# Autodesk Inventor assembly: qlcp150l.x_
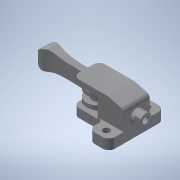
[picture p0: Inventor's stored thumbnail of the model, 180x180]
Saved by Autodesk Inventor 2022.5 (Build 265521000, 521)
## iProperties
Part Number: qlcp150l.x_
Material: 一般
Document SubType Name: Assembly
Designer: ImaoCorp
Sending System: SOLIDWORKS 2017-2017317
MC: AMD64
MC_MODEL: Intel64 Family 6 Model 60 Stepping 3, GenuineIntel
OS: Windows_NT
FRU: Parasolid Version 29.0, build 201,  4-17-2017
FORMAT: text
GUISE: transmit
KEY: qlcp150l
FILE: qlcp150l.x_t
DATE: Wed Sep 04 15:45:31 2019
Author: ImaoCorp
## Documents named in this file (4)
- X:\14_SW2022-Inv2022\00_全2023-1023新製品(TCC)まで\q\qlcp150l\QLCP150L.iam
- X:\14_SW2022-Inv2022\00_全2023-1023新製品(TCC)まで\q\qlcp150l\qlcp150l_01.ipt
- X:\14_SW2022-Inv2022\00_全2023-1023新製品(TCC)まで\q\qlcp150l\qlcp150l_02.ipt
- X:\14_SW2022-Inv2022\00_全2023-1023新製品(TCC)まで\q\qlcp150l\qlcp150l_03.ipt
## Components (3 placed, 3 different names)
1. qlcp150l_01
2. qlcp150l_02
3. qlcp150l_03
